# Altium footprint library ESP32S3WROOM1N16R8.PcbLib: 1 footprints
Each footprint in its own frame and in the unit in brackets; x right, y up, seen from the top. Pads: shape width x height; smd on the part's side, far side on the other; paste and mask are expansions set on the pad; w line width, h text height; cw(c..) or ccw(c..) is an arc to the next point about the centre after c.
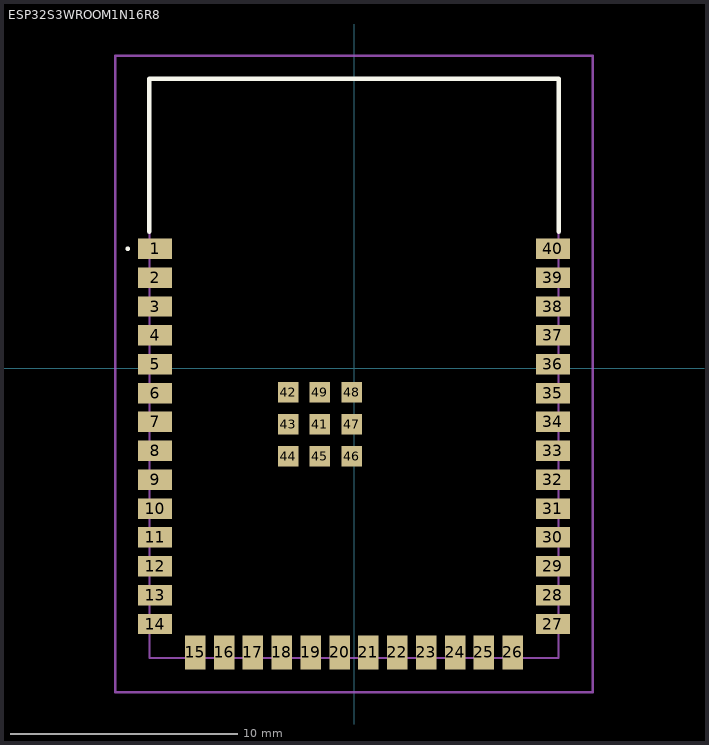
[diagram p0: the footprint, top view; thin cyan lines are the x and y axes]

## ESP32S3WROOM1N16R8 [mm]
pads (49):
  rect 1.5x0.9 smd: 1(-8.75,5.26) 2(-8.75,3.99) 3(-8.75,2.72) 4(-8.75,1.45) 5(-8.75,0.18) 6(-8.75,-1.09) 7(-8.75,-2.36) 8(-8.75,-3.63) 9(-8.75,-4.9) 10(-8.75,-6.17) 11(-8.75,-7.44) 12(-8.75,-8.71) 13(-8.75,-9.98) 14(-8.75,-11.25) 27(8.75,-11.25) 28(8.75,-9.98) 29(8.75,-8.71) 30(8.75,-7.44) 31(8.75,-6.17) 32(8.75,-4.9) 33(8.75,-3.63) 34(8.75,-2.36) 35(8.75,-1.09) 36(8.75,0.18) 37(8.75,1.45) 38(8.75,2.72) 39(8.75,3.99) 40(8.75,5.26)
  rect 0.9x1.5 smd: 15(-6.985,-12.5) 16(-5.715,-12.5) 17(-4.445,-12.5) 18(-3.175,-12.5) 19(-1.905,-12.5) 20(-0.635,-12.5) 21(0.635,-12.5) 22(1.905,-12.5) 23(3.175,-12.5) 24(4.445,-12.5) 25(5.715,-12.5) 26(6.985,-12.5)
  rect 0.9x0.9 smd: 41(-1.5,-2.46) 42(-2.9,-1.06) 43(-2.9,-2.46) 44(-2.9,-3.86) 45(-1.5,-3.86) 46(-0.1,-3.86) 47(-0.1,-2.46) 48(-0.1,-1.06) 49(-1.5,-1.06)
Top Overlay:
  lines w0.1: -10,5.26 cw(c-9.95,5.26) -9.9,5.26 ; -10,5.26 -10,5.26 ; -10,5.26 ccw(c-9.95,5.26) -9.9,5.26 ; -9.9,5.26 -9.9,5.26
  lines w0.2: -9,6 -9,12.75 9,12.75 9,6
Mechanical 15:
  lines w0.1: -9,-12.75 9,-12.75 9,12.75 -9,12.75 -9,-12.75
Mechanical 20:
  lines w0.1: -10.5,-14.25 10.5,-14.25 10.5,13.75 -10.5,13.75 -10.5,-14.25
